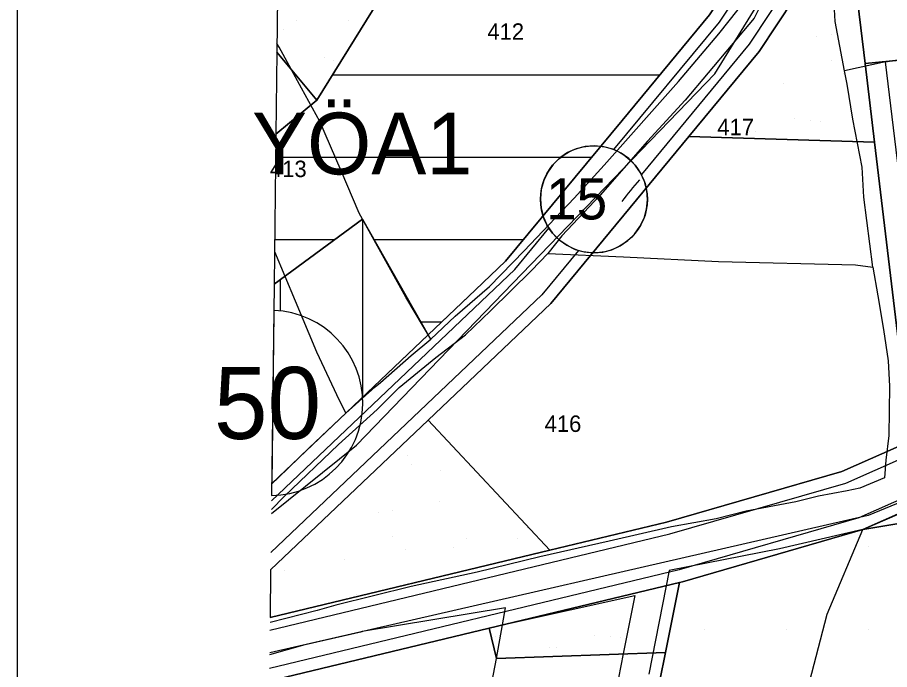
# Model space of a CAD drawing. Extents: x 410727 to 412947, y 4463506 to 4466382.
# Drawn here: x 410732.3 to 410944.2, y 4466006.6 to 4466165.1 of the extents above; entities that cross this region are included whole.
import ezdxf

# ---------------------------------------------------------------- set-up
doc = ezdxf.new("R2010")
doc.units = 0
for name, color, linetype in [('ADAKENARI', 7, 'Continuous'), ('KALDIRIM', 7, 'Continuous'), ('KDS_PARSEL_NO', 7, 'Continuous'), ('KDS_PL', 7, 'Continuous'), ('LJ_ÇERÇEVE', 7, 'Continuous'), ('PL_AYA_PARK_DINLENME', 7, 'Continuous'), ('PL_K_BHA', 7, 'Continuous'), ('PL_K_TALI_IS_MER', 7, 'Continuous'), ('PL_KON_MEV_050', 7, 'Continuous'), ('PL_KON_ONE_50', 7, 'Continuous'), ('PL_OZEL_EGITIM', 7, 'Continuous'), ('sembol', 7, 'Continuous'), ('sm_yol_beyaz', 7, 'Continuous'), ('sm_yol_genisligi', 7, 'Continuous'), ('TR_AZYOGUNLUK_MESKUN', 7, 'Continuous'), ('TR_GELİŞME_KONUT_ÇOKAZ', 7, 'Continuous'), ('TR_OZEL_EGITIM', 7, 'Continuous'), ('TR_PARKALANI', 7, 'Continuous'), ('TR_TİCARET', 7, 'Continuous'), ('YAZI_jeolojik_durum', 7, 'Continuous'), ('Yerlesime_uygunluk_sınırı', 7, 'Continuous')]:
    doc.layers.add(name, color=color, linetype=linetype)

msp = doc.modelspace()

# ---------------------------------------------------------------- linework, layer by layer
at = {"layer": 'ADAKENARI'}
for p, q in [((410938.28, 4466153.9), (410934.05, 4466189.23)), ((410984.99, 4466158.37), (410938.28, 4466153.9)), ((410879.24, 4466140.03), (410850.95, 4466105.81)), ((410850.95, 4466105.81), (410843.66, 4466098.87)), ((410843.66, 4466098.87), (410794.1, 4466051.75))]:
    msp.add_line(p, q, dxfattribs=at)
for points in [[(410795.11, 4466136.69), (410805.11, 4466144.92), (410866.88, 4466244.62), (410833.32, 4466279.27), (410832.84, 4466307.82), (410865.03, 4466330.16), (410877.28, 4466326.74), (410905.8, 4466318.77), (410931.26, 4466291.1), (410937.01, 4466220.86), (410900.49, 4466165.73), (410879.24, 4466140.03), (410850.95, 4466105.81), (410843.66, 4466098.87), (410832.15, 4466087.93), (410816.2, 4466116.02), (410794.68, 4466100.2)], [(410796.46, 4466250.92), (410833.32, 4466279.27), (410866.88, 4466244.62), (410856.65, 4466241.61), (410854.49, 4466243.9), (410849.71, 4466249.6), (410844.2, 4466253.37), (410840.27, 4466253.16), (410836.39, 4466251.28), (410830.37, 4466248.16), (410827.75, 4466246.92), (410822.57, 4466243.9), (410812.36, 4466237.47), (410798.29, 4466228.95), (410807.2, 4466213.12), (410820.24, 4466219.87), (410827.53, 4466223.46), (410843.7, 4466233.54), (410856.65, 4466241.61), (410866.88, 4466244.62), (410805.11, 4466144.92)], [(410940.58, 4466134.71), (410895.48, 4466136.13), (410912.56, 4466156.78), (410934.05, 4466189.23), (410938.28, 4466153.9), (410940.58, 4466134.71)], [(411019.64, 4466094.39), (410946.16, 4466088.17), (410940.58, 4466134.71), (410938.28, 4466153.9), (410984.99, 4466158.37), (411018.73, 4466159.08), (411019.64, 4466094.39)], [(410805.11, 4466144.92), (410795.35, 4466156.58)], [(410940.58, 4466134.71), (410946.16, 4466088.17), (410949.29, 4466062.09), (410932.63, 4466054.71), (410890.07, 4466042.42), (410861.68, 4466035.58), (410832.1, 4466067.18), (410861.94, 4466095.56), (410895.48, 4466136.13), (410940.58, 4466134.71)], [(411073.95, 4466063.4), (410937.77, 4466040.58), (411016.83, 4466075.63), (411040.65, 4466079.02), (411076.34, 4466074.17), (411073.95, 4466063.4)], [(410793.85, 4466030.82), (410832.1, 4466067.18), (410861.68, 4466035.58), (410793.72, 4466019.23)], [(410887.08, 4465997.07), (410889.8, 4466010.71), (410893.2, 4466027.74), (410893.9, 4466027.91), (410937.77, 4466040.58), (411073.95, 4466063.4), (411064.87, 4466022.46), (411041.23, 4465915.91), (410930.02, 4465892.38), (410878.63, 4465910.07), (410880.97, 4465951.25), (410881.64, 4465963), (410882.74, 4465970.47), (410885.14, 4465986.69), (410887.08, 4465997.07)], [(410846.93, 4466016.61), (410893.2, 4466027.74), (410889.8, 4466010.71), (410848.7, 4466009.27), (410846.93, 4466016.61)], [(410793.47, 4465998.47), (410795.43, 4466004.21), (410846.93, 4466016.61), (410848.7, 4466009.27), (410889.8, 4466010.71), (410887.08, 4465997.07), (410885.14, 4465986.69), (410882.74, 4465970.47), (410881.64, 4465963), (410880.97, 4465951.25), (410878.63, 4465910.07), (410863.39, 4465915.31), (410854.96, 4465915.37), (410834, 4465913.99)]]:
    msp.add_lwpolyline(points, dxfattribs=at)
msp.add_arc((410931.92, 4466082.26), 65, 138.1798, 144.1944, dxfattribs=at)
at = {"layer": 'KALDIRIM'}
for points in [[(410877.26, 4466132.92), (410902.91, 4466163.94), (410984.73, 4466287.49), (410992.24, 4466282.52), (410910.15, 4466158.57), (410883.93, 4466126.86)], [(410794.05, 4466047.57), (410853.15, 4466103.76), (410861.47, 4466113.82)], [(410868.67, 4466108.41), (410859.74, 4466097.61), (410793.9, 4466035.01)], [(410793.68, 4466016.13), (410890.83, 4466039.51), (410933.65, 4466051.88), (410962.82, 4466064.81)], [(410966.29, 4466056.5), (410936.74, 4466043.41), (410893.14, 4466030.81), (410793.57, 4466006.85)]]:
    msp.add_lwpolyline(points, dxfattribs=at)
at = {"layer": 'KDS_PL'}
for p, q in [((410914.66, 4466171.57), (410911.33, 4466164.9)), ((410931.03, 4466164.06), (410930.61, 4466171.31)), ((410902.77, 4466161.05), (410909.67, 4466169.8)), ((410911.33, 4466164.9), (410894.61, 4466144.97)), ((410933.26, 4466152.08), (410931.03, 4466164.06)), ((410892.92, 4466149.48), (410902.77, 4466161.05)), ((410795.91, 4466157.81), (410795.37, 4466158.72)), ((410801.34, 4466147.89), (410795.91, 4466157.81)), ((410943.27, 4466154.29), (410950.62, 4466155.49)), ((410943.27, 4466154.29), (410933.26, 4466152.08)), ((410950.69, 4466092.45), (410943.27, 4466154.29)), ((410933.95, 4466148.87), (410933.26, 4466152.08)), ((410874.9, 4466129.17), (410892.92, 4466149.48)), ((410935.34, 4466140.37), (410933.95, 4466148.87)), ((410805.81, 4466139.78), (410801.34, 4466147.89)), ((410894.61, 4466144.97), (410885.46, 4466134.95)), ((410937.57, 4466128.66), (410935.34, 4466140.37)), ((410811, 4466127.8), (410805.81, 4466139.78)), ((410885.46, 4466134.95), (410873.91, 4466121.83)), ((410815.35, 4466117.51), (410811, 4466127.8)), ((410867.57, 4466121.13), (410874.9, 4466129.17)), ((410937.99, 4466121.41), (410937.57, 4466128.66)), ((410873.91, 4466121.83), (410864.62, 4466111.96)), ((410940.16, 4466104.34), (410937.99, 4466121.41)), ((410855.46, 4466108.29), (410867.57, 4466121.13)), ((410826.71, 4466097.06), (410815.35, 4466117.51)), ((410864.62, 4466111.96), (410861.24, 4466107.72)), ((410794.77, 4466108.16), (410799.77, 4466096.21)), ((410847.02, 4466099.68), (410855.46, 4466108.29)), ((410857.23, 4466103.58), (410861.24, 4466107.72)), ((410861.24, 4466107.72), (410879.61, 4466106.88)), ((410879.61, 4466106.88), (410902.7, 4466105.75)), ((410902.7, 4466105.75), (410935.93, 4466104.9)), ((410935.93, 4466104.9), (410940.16, 4466104.34)), ((410940.16, 4466104.34), (410941.42, 4466097.41)), ((410847.27, 4466093.75), (410857.23, 4466103.58)), ((410838.71, 4466092.49), (410847.02, 4466099.68)), ((410799.77, 4466096.21), (410804.97, 4466083.75)), ((410832.74, 4466086.89), (410826.71, 4466097.06)), ((410941.42, 4466097.41), (410942.78, 4466089.22)), ((410841.18, 4466087.93), (410847.27, 4466093.75)), ((410832.74, 4466086.89), (410838.71, 4466092.49)), ((410834.01, 4466082.4), (410841.18, 4466087.93)), ((410942.78, 4466089.22), (410943.86, 4466081.61)), ((410828.03, 4466082.9), (410832.74, 4466086.89)), ((410804.97, 4466083.75), (410810.52, 4466072)), ((410820.55, 4466076.36), (410828.03, 4466082.9)), ((410825.06, 4466075.08), (410834.01, 4466082.4)), ((410943.86, 4466081.61), (410944.22, 4466075.44)), ((410812.09, 4466068.86), (410819.22, 4466075.27)), ((410819.22, 4466075.27), (410820.55, 4466076.36)), ((410819.75, 4466069.77), (410825.06, 4466075.08)), ((410944.22, 4466075.44), (410944.07, 4466063.45)), ((410810.52, 4466072), (410812.09, 4466068.86)), ((410803.23, 4466060.46), (410812.09, 4466068.86)), ((410810.37, 4466061.22), (410819.75, 4466069.77)), ((410944.07, 4466063.45), (410943.36, 4466057.49)), ((410795.76, 4466053.27), (410803.23, 4466060.46)), ((410797.11, 4466048.59), (410810.37, 4466061.22)), ((410943.36, 4466057.49), (410943, 4466053.18)), ((410794.1, 4466051.68), (410795.76, 4466053.27)), ((410943, 4466053.18), (410936.98, 4466050.67)), ((410933.97, 4466050.02), (410926.95, 4466048.66)), ((410936.98, 4466050.67), (410933.97, 4466050.02)), ((410794.03, 4466045.5), (410797.11, 4466048.59)), ((410921.5, 4466047.29), (410909.39, 4466045.07)), ((410926.95, 4466048.66), (410921.5, 4466047.29)), ((410937.77, 4466040.58), (410956.89, 4466048.9)), ((410909.39, 4466045.07), (410902.08, 4466043.2)), ((410902.08, 4466043.2), (410891.27, 4466041.26)), ((410891.27, 4466041.26), (410876.07, 4466037.75)), ((410937.76, 4466040.58), (410917.51, 4466035.93)), ((410929.06, 4466020.01), (410937.77, 4466040.58)), ((410876.07, 4466037.75), (410859.23, 4466033.94)), ((410917.51, 4466035.93), (410890.68, 4466030.6)), ((410859.23, 4466033.94), (410844.04, 4466030.21)), ((410844.04, 4466030.21), (410828, 4466026.76)), ((410890.68, 4466030.6), (410885.76, 4466005.44)), ((410828, 4466026.76), (410809.65, 4466022.17)), ((410850.19, 4466017.39), (410882.37, 4466024.58)), ((410882.37, 4466024.58), (410879.53, 4466010.35)), ((410809.65, 4466022.17), (410805.14, 4466020.95)), ((410805.14, 4466020.95), (410793.7, 4466018)), ((410850.95, 4466021.53), (410816.07, 4466015.81)), ((410850.19, 4466017.39), (410850.95, 4466021.53)), ((410922.37, 4465994.25), (410929.06, 4466020.01)), ((410802.26, 4466012.67), (410816.07, 4466015.81)), ((410848.7, 4466009.27), (410850.19, 4466017.39)), ((410793.61, 4466010.25), (410802.26, 4466012.67)), ((410845.08, 4465989.6), (410848.7, 4466009.27)), ((410848.7, 4466009.27), (410879.53, 4466010.35)), ((410879.53, 4466010.35), (410875.66, 4465990.98))]:
    msp.add_line(p, q, dxfattribs=at)
at = {"layer": 'LJ_ÇERÇEVE'}
msp.add_lwpolyline([(410732.32, 4466381.6), (412946.74, 4466381.6), (412946.74, 4463506.16), (410732.32, 4463506.16)], close=True, dxfattribs=at)
at = {"layer": 'PL_AYA_PARK_DINLENME'}
for points in [[(410796.46, 4466250.92), (410795.35, 4466156.58), (410805.11, 4466144.92), (410866.88, 4466244.62), (410833.32, 4466279.27), (410796.46, 4466250.92)], [(410938.28, 4466153.9), (410934.05, 4466189.23), (410912.56, 4466156.78), (410895.48, 4466136.13), (410940.58, 4466134.71), (410938.28, 4466153.9)], [(411073.95, 4466063.4), (411076.34, 4466074.17), (411040.65, 4466079.02), (411016.83, 4466075.63), (410937.77, 4466040.58), (411073.95, 4466063.4)], [(410793.85, 4466030.82), (410793.72, 4466019.23), (410861.68, 4466035.58), (410832.1, 4466067.18), (410793.85, 4466030.82)], [(410848.7, 4466009.27), (410889.8, 4466010.71), (410893.2, 4466027.74), (410846.93, 4466016.61), (410848.7, 4466009.27)]]:
    msp.add_lwpolyline(points, dxfattribs=at)
at = {"layer": 'PL_K_BHA'}
msp.add_lwpolyline([(410795.35, 4466156.58), (410795.11, 4466136.69), (410805.11, 4466144.92), (410795.35, 4466156.58)], dxfattribs=at)
at = {"layer": 'PL_K_TALI_IS_MER'}
msp.add_lwpolyline([(410946.16, 4466088.17), (410940.58, 4466134.71), (410895.48, 4466136.13), (410861.94, 4466095.56), (410832.1, 4466067.18), (410861.68, 4466035.58), (410890.07, 4466042.42), (410932.63, 4466054.71), (410949.29, 4466062.09), (410946.16, 4466088.17)], dxfattribs=at)
at = {"layer": 'PL_KON_MEV_050'}
for points in [[(411018.73, 4466159.08), (410984.99, 4466158.37), (410938.28, 4466153.9), (410940.58, 4466134.71), (410946.16, 4466088.17), (411019.64, 4466094.39), (411018.73, 4466159.08)], [(410794.68, 4466100.2), (410794.1, 4466051.75), (410832.15, 4466087.93), (410832.15, 4466087.93), (410816.2, 4466116.02), (410794.68, 4466100.2)]]:
    msp.add_lwpolyline(points, dxfattribs=at)
at = {"layer": 'PL_KON_ONE_50'}
for points in [[(410816.68, 4466331), (410797.42, 4466331.23), (410796.46, 4466250.92), (410833.32, 4466279.27), (410866.88, 4466244.62), (410805.11, 4466144.92), (410795.11, 4466136.69), (410794.68, 4466100.2), (410816.2, 4466116.02), (410832.15, 4466087.93), (410843.66, 4466098.87), (410850.95, 4466105.81), (410879.24, 4466140.03), (410900.49, 4466165.73), (410937.01, 4466220.86), (410931.26, 4466291.1), (410905.8, 4466318.77), (410877.28, 4466326.74), (410865.03, 4466330.16), (410861.62, 4466327.79), (410841.62, 4466313.92), (410832.84, 4466307.82), (410821.62, 4466323.91), (410816.68, 4466331)], [(411018.73, 4466159.08), (411019.64, 4466094.39), (411040.6, 4466094.16), (411083.21, 4466088.38), (411127.43, 4466096.15), (411139.34, 4466102.02), (411143.99, 4466106.28), (411135.74, 4466178.25), (411069.2, 4466174.92), (411071.88, 4466196.56), (411061.36, 4466220.11), (411049.97, 4466245.63), (410970.35, 4466244.04), (410934.05, 4466189.23), (410938.28, 4466153.9), (410984.99, 4466158.37), (411018.73, 4466159.08)], [(410793.47, 4465998.47), (410792.37, 4465905.41), (410834, 4465913.99), (410854.96, 4465915.37), (410863.39, 4465915.31), (410878.63, 4465910.07), (410880.97, 4465951.25), (410881.64, 4465963), (410882.74, 4465970.47), (410885.14, 4465986.69), (410887.08, 4465997.07), (410889.8, 4466010.71), (410848.7, 4466009.27), (410846.93, 4466016.61), (410795.43, 4466004.21), (410793.47, 4465998.47)]]:
    msp.add_lwpolyline(points, dxfattribs=at)
at = {"layer": 'PL_OZEL_EGITIM'}
msp.add_lwpolyline([(410887.08, 4465997.07), (410885.14, 4465986.69), (410882.74, 4465970.47), (410881.64, 4465963), (410880.97, 4465951.25), (410878.63, 4465910.07), (410930.02, 4465892.38), (411041.23, 4465915.91), (411064.87, 4466022.46), (411073.95, 4466063.4), (410937.77, 4466040.58), (410893.9, 4466027.91), (410893.2, 4466027.74), (410889.8, 4466010.71), (410887.08, 4465997.07)], dxfattribs=at)
at = {"layer": 'sembol'}
msp.add_lwpolyline([(410794.6, 4466093.84), (410794.07, 4466048.86)], dxfattribs=at)
msp.add_arc((410793.75, 4466071.36), 22.5, 270.8067, 87.8342, dxfattribs=at)
at = {"layer": 'sm_yol_beyaz'}
msp.add_lwpolyline([(410885.4, 4466120.74), (410885.22, 4466122.99), (410884.66, 4466125.19), (410883.72, 4466127.25), (410882.44, 4466129.12), (410880.85, 4466130.74), (410879.01, 4466132.06), (410876.96, 4466133.04), (410874.78, 4466133.64), (410872.52, 4466133.86), (410870.26, 4466133.69), (410868.07, 4466133.12), (410866.01, 4466132.19), (410864.14, 4466130.9), (410862.52, 4466129.32), (410861.2, 4466127.47), (410860.22, 4466125.43), (410859.62, 4466123.25), (410859.4, 4466120.99), (410859.57, 4466118.73), (410860.14, 4466116.54), (410861.07, 4466114.47), (410862.35, 4466112.61), (410863.94, 4466110.99), (410865.79, 4466109.67), (410867.83, 4466108.69), (410870.01, 4466108.08), (410872.27, 4466107.86), (410874.53, 4466108.04), (410876.72, 4466108.6), (410878.79, 4466109.54), (410880.65, 4466110.82), (410882.27, 4466112.41), (410883.59, 4466114.25), (410884.57, 4466116.3), (410885.18, 4466118.48), (410885.4, 4466120.74)], dxfattribs=at)
at = {"layer": 'sm_yol_genisligi'}
msp.add_circle((410872.4, 4466120.86), 13, dxfattribs=at)
at = {"layer": 'TR_AZYOGUNLUK_MESKUN'}
for p, q in [((410816.22, 4466072.79), (410816.22, 4466115.98)), ((410796.22, 4466093.72), (410796.22, 4466101.34))]:
    msp.add_line(p, q, dxfattribs=at)
msp.add_lwpolyline([(410794.1, 4466051.75), (410832.15, 4466087.93), (410816.2, 4466116.02), (410794.68, 4466100.2)], dxfattribs=at)
at = {"layer": 'TR_GELİŞME_KONUT_ÇOKAZ'}
for p, q in [((410808.92, 4466151.07), (410888.37, 4466151.07)), ((410795.04, 4466131.07), (410871.84, 4466131.07)), ((410794.81, 4466111.07), (410809.45, 4466111.07)), ((410819.01, 4466111.07), (410855.3, 4466111.07)), ((410830.37, 4466091.07), (410835.45, 4466091.07))]:
    msp.add_line(p, q, dxfattribs=at)
msp.add_lwpolyline([(410792.37, 4465905.41), (410834, 4465913.99), (410854.96, 4465915.37), (410863.39, 4465915.31), (410878.63, 4465910.07), (410880.97, 4465951.25), (410881.64, 4465963), (410882.74, 4465970.47), (410885.14, 4465986.69), (410887.08, 4465997.07), (410889.8, 4466010.71), (410848.7, 4466009.27), (410846.93, 4466016.61), (410795.43, 4466004.21), (410793.47, 4465998.47)], dxfattribs=at)
at = {"layer": 'TR_OZEL_EGITIM'}
for p, q in [((410939.22, 4466036.41), (410939.22, 4466036.41)), ((410899.22, 4466016.41), (410899.22, 4466016.41)), ((410919.22, 4466016.41), (410919.22, 4466016.41)), ((410939.22, 4466016.41), (410939.22, 4466016.41))]:
    msp.add_line(p, q, dxfattribs=at)
at = {"layer": 'TR_PARKALANI'}
for p, q in [((410800.17, 4466164.31), (410800.17, 4466164.31)), ((410800.17, 4466164.31), (410800.17, 4466164.31)), ((410812.7, 4466164.42), (410812.7, 4466164.42)), ((410797.06, 4466162.1), (410797.06, 4466162.1)), ((410916.12, 4466162.03), (410916.12, 4466162.03)), ((410926.48, 4466160.49), (410926.48, 4466160.49)), ((410926.48, 4466160.49), (410926.48, 4466160.49)), ((410930.03, 4466160.91), (410930.03, 4466160.91)), ((410930.03, 4466160.91), (410930.03, 4466160.91)), ((410806.83, 4466155.33), (410806.83, 4466155.33)), ((410806.83, 4466155.33), (410806.83, 4466155.33)), ((410809.23, 4466154.56), (410809.23, 4466154.56)), ((410930.03, 4466154.5), (410930.03, 4466154.5)), ((410933.14, 4466151.51), (410933.14, 4466151.51)), ((410933.14, 4466151.51), (410933.14, 4466151.51)), ((410918.37, 4466148.9), (410918.37, 4466148.9)), ((410918.37, 4466148.9), (410918.37, 4466148.9)), ((410921.14, 4466140.39), (410921.14, 4466140.39)), ((410925.03, 4466139.92), (410925.03, 4466139.92)), ((410925.03, 4466139.92), (410925.03, 4466139.92)), ((410927.42, 4466139.73), (410927.42, 4466139.73)), ((410910.26, 4466137.32), (410910.26, 4466137.32)), ((410910.26, 4466137.32), (410910.26, 4466137.32)), ((410911.78, 4466137.41), (410911.78, 4466137.41)), ((410827.01, 4466058.51), (410827.01, 4466058.51)), ((410828.1, 4466056.38), (410828.1, 4466056.38)), ((410828.1, 4466056.38), (410828.1, 4466056.38)), ((410835.03, 4466054.86), (410835.03, 4466054.86)), ((410834.76, 4466047.4), (410834.76, 4466047.4)), ((410834.76, 4466047.4), (410834.76, 4466047.4)), ((410823.54, 4466045.21), (410823.54, 4466045.21)), ((410823.54, 4466045.21), (410823.54, 4466045.21)), ((410819.98, 4466044.79), (410819.98, 4466044.79)), ((410819.98, 4466044.79), (410819.98, 4466044.79)), ((410856.19, 4466041.02), (410856.19, 4466041.02)), ((410856.19, 4466041.02), (410856.19, 4466041.02)), ((410823.53, 4466038.81), (410823.53, 4466038.81)), ((410841.42, 4466038.42), (410841.42, 4466038.42)), ((410841.42, 4466038.42), (410841.42, 4466038.42)), ((410853.95, 4466038.53), (410853.95, 4466038.53)), ((410826.65, 4466035.81), (410826.65, 4466035.81)), ((410826.65, 4466035.81), (410826.65, 4466035.81)), ((410838.31, 4466036.21), (410838.31, 4466036.21)), ((410811.87, 4466033.21), (410811.87, 4466033.21)), ((410811.87, 4466033.21), (410811.87, 4466033.21)), ((410797.1, 4466030.6), (410797.1, 4466030.6)), ((410797.1, 4466030.6), (410797.1, 4466030.6)), ((410814.64, 4466024.7), (410814.64, 4466024.7)), ((410848.46, 4466014.57), (410848.46, 4466014.57)), ((410872.59, 4466014.95), (410872.59, 4466014.95)), ((410876.48, 4466014.48), (410876.48, 4466014.48)), ((410876.48, 4466014.48), (410876.48, 4466014.48)), ((410878.87, 4466014.29), (410878.87, 4466014.29)), ((410861.71, 4466011.88), (410861.71, 4466011.88)), ((410861.71, 4466011.88), (410861.71, 4466011.88)), ((410863.23, 4466011.97), (410863.23, 4466011.97))]:
    msp.add_line(p, q, dxfattribs=at)
at = {"layer": 'TR_TİCARET'}
msp.add_lwpolyline([(410932.63, 4466054.71), (410949.29, 4466062.09), (410946.16, 4466088.17), (410940.58, 4466134.71), (410895.48, 4466136.13), (410861.94, 4466095.56), (410832.1, 4466067.18), (410861.68, 4466035.58), (410890.07, 4466042.42), (410932.63, 4466054.71)], dxfattribs=at)
at = {"layer": 'Yerlesime_uygunluk_sınırı'}
for points in [[(410794.02, 4466044.48), (410814.72, 4466061.06), (410872.79, 4466121.33), (410901.75, 4466151.38), (410931.46, 4466199.49)], [(411249.96, 4466080.27), (411207.16, 4466048.84), (411087.92, 4466058.92), (411061.58, 4466077.97), (411022.9, 4466078.53), (410939.01, 4466044.04), (410793.61, 4466010.63)]]:
    msp.add_lwpolyline(points, dxfattribs=at)

# ---------------------------------------------------------------- texts
at = {"layer": 'KDS_PARSEL_NO'}
for s, p in [('412', (410846.5, 4466159.62)), ('417', (410902.38, 4466136.42)), ('413', (410793.67, 4466126.25)), ('416', (410860.42, 4466064.31))]:
    msp.add_text(s, height=4, dxfattribs=at).set_placement(p)
at = {"layer": 'sembol'}
msp.add_text('50', height=17.5, dxfattribs=at).set_placement((410780.08, 4466062.61))
at = {"layer": 'sm_yol_genisligi'}
msp.add_text('15', height=10, dxfattribs=at).set_placement((410860.76, 4466115.96))
at = {"layer": 'YAZI_jeolojik_durum'}
msp.add_text('YÖA1', height=15, dxfattribs=at).set_placement((410789.32, 4466126.92))

doc.saveas('drawing.dxf')
